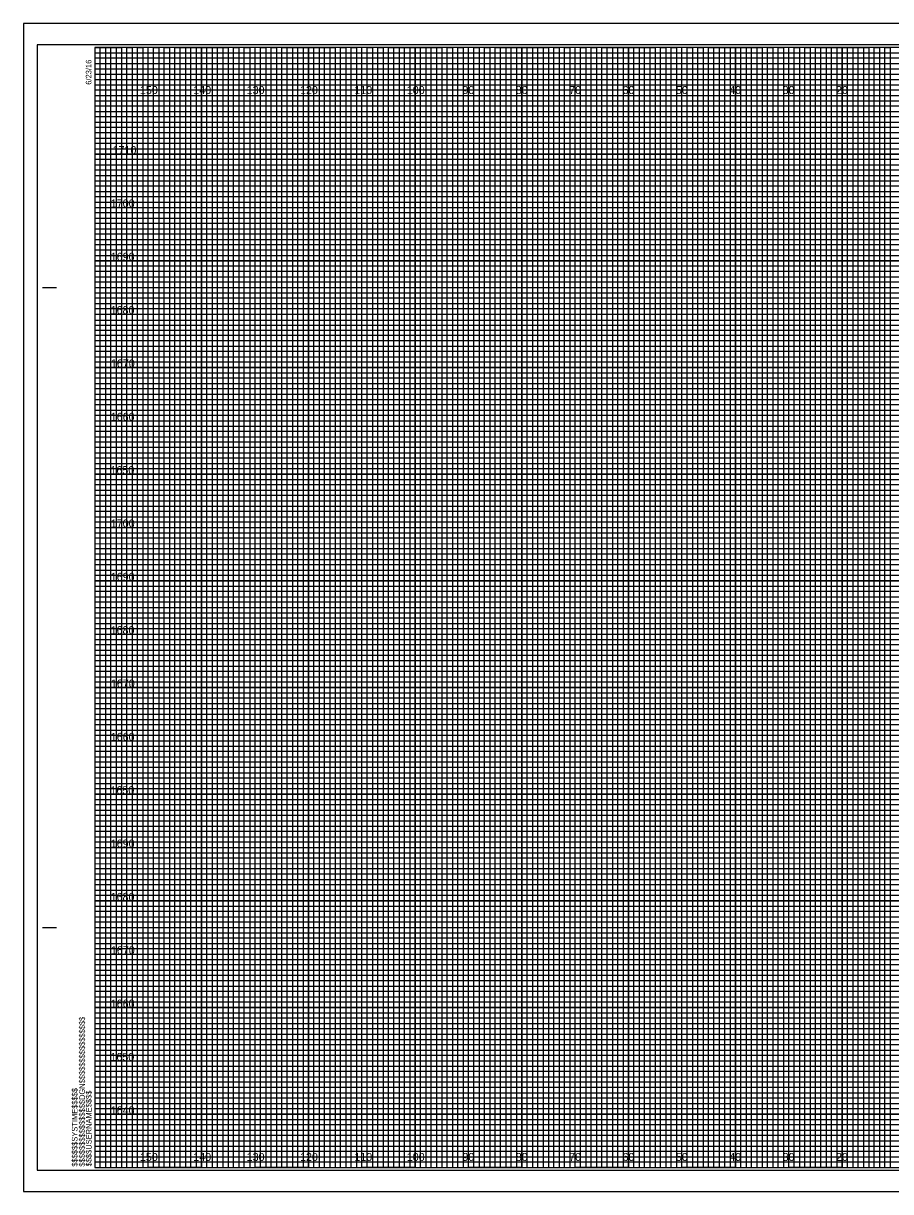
# Model space of a CAD drawing. Extents: x -13 to 323, y -5 to 2414.
# Drawn here: x -13.4 to 149.1, y 1535.5 to 1754.5 of the extents above; entities that cross this region are included whole.
import ezdxf

# ---------------------------------------------------------------- set-up
doc = ezdxf.new("R2010")
doc.units = 0
for name, color, linetype in [('Prop XS Elevation Labels', 7, 'Continuous'), ('Prop XS Offset Labels', 7, 'Continuous'), ('Sheet Cross Section CELL', 7, 'Continuous'), ('Sheet Cross Section Grid Major CELL', 7, 'Continuous'), ('Sheet Cross Section Grid Middle CELL', 7, 'Continuous'), ('Sheet Cross Section Grid Minor 1 CELL', 7, 'Continuous'), ('Sheet Cross Section Grid Minor 2 CELL', 7, 'Continuous'), ('Sheet Cutting Line CELL', 7, 'Continuous'), ('Sheet DOT Grid CELL', 7, 'Continuous'), ('Sheet Plot Border Inside CELL', 7, 'Continuous'), ('Sheet Plot Border Outside CELL', 7, 'Continuous')]:
    doc.layers.add(name, color=color, linetype=linetype)

msp = doc.modelspace()

# ---------------------------------------------------------------- linework, layer by layer
at = {"layer": 'Sheet Cross Section CELL'}
for p, q in [((-9.8, 1705), (-7.3, 1705)), ((-9.7, 1705), (-7.2, 1705)), ((-9.8, 1585), (-7.3, 1585)), ((-9.7, 1585), (-7.2, 1585)), ((0, 1540), (0, 1540)), ((0, 1540), (0, 1540)), ((0, 1540), (0, 1540)), ((0, 1540), (0, 1540)), ((0, 1540), (0, 1540)), ((0, 1540), (0, 1540)), ((0, 1540), (0, 1540))]:
    msp.add_line(p, q, dxfattribs=at)
msp.add_lwpolyline([(320, 1750), (0, 1750), (0, 1540), (320, 1540)], close=True, dxfattribs=at)
at = {"layer": 'Sheet Cross Section Grid Major CELL'}
for p, q in [((10, 1750), (0, 1750)), ((10, 1540), (10, 1750)), ((30, 1750), (20, 1750)), ((20, 1750), (20, 1540)), ((30, 1540), (30, 1750)), ((50, 1750), (40, 1750)), ((40, 1750), (40, 1540)), ((50, 1540), (50, 1750)), ((70, 1750), (60, 1750)), ((60, 1750), (60, 1540)), ((70, 1540), (70, 1750)), ((90, 1750), (80, 1750)), ((80, 1750), (80, 1540)), ((90, 1540), (90, 1750)), ((110, 1750), (100, 1750)), ((100, 1750), (100, 1540)), ((110, 1540), (110, 1750)), ((130, 1750), (120, 1750)), ((120, 1750), (120, 1540)), ((130, 1540), (130, 1750)), ((150, 1750), (140, 1750)), ((140, 1750), (140, 1540)), ((20, 1540), (10, 1540)), ((40, 1540), (30, 1540)), ((60, 1540), (50, 1540)), ((80, 1540), (70, 1540)), ((100, 1540), (90, 1540)), ((120, 1540), (110, 1540)), ((140, 1540), (130, 1540))]:
    msp.add_line(p, q, dxfattribs=at)
for points in [[(0, 1740), (320, 1740), (320, 1730), (0, 1730)], [(0, 1720), (320, 1720), (320, 1710), (0, 1710)], [(0, 1700), (320, 1700), (320, 1690), (0, 1690)], [(0, 1680), (320, 1680), (320, 1670), (0, 1670)], [(0, 1660), (320, 1660), (320, 1650), (0, 1650)], [(0, 1640), (320, 1640), (320, 1630), (0, 1630)], [(0, 1620), (320, 1620), (320, 1610), (0, 1610)], [(0, 1600), (320, 1600), (320, 1590), (0, 1590)], [(0, 1580), (320, 1580), (320, 1570), (0, 1570)], [(0, 1560), (320, 1560), (320, 1550), (0, 1550)]]:
    msp.add_lwpolyline(points, dxfattribs=at)
at = {"layer": 'Sheet Cross Section Grid Middle CELL'}
for points in [[(0, 1750), (5, 1750), (5, 1540), (15, 1540), (15, 1750), (25, 1750), (25, 1540), (35, 1540), (35, 1750), (45, 1750), (45, 1540), (55, 1540), (55, 1750), (65, 1750), (65, 1540), (75, 1540), (75, 1750), (85, 1750), (85, 1540), (95, 1540), (95, 1750), (105, 1750), (105, 1540), (115, 1540), (115, 1750), (125, 1750), (125, 1540), (135, 1540), (135, 1750), (145, 1750), (145, 1540), (155, 1540)], [(0, 1745), (275, 1745)], [(0, 1725), (320, 1725), (320, 1735), (0, 1735)], [(0, 1705), (320, 1705), (320, 1715), (0, 1715)], [(0, 1685), (320, 1685), (320, 1695), (0, 1695)], [(0, 1665), (320, 1665), (320, 1675), (0, 1675)], [(0, 1645), (320, 1645), (320, 1655), (0, 1655)], [(0, 1625), (320, 1625), (320, 1635), (0, 1635)], [(0, 1605), (320, 1605), (320, 1615), (0, 1615)], [(0, 1585), (320, 1585), (320, 1595), (0, 1595)], [(0, 1565), (320, 1565), (320, 1575), (0, 1575)], [(0, 1545), (320, 1545), (320, 1555), (0, 1555)]]:
    msp.add_lwpolyline(points, dxfattribs=at)
at = {"layer": 'Sheet Cross Section Grid Minor 1 CELL'}
for p, q in [((0, 1749), (260, 1749)), ((260, 1747.98), (0, 1747.98)), ((0, 1747.98), (0, 1747)), ((0, 1747), (260, 1747)), ((260, 1745.89), (0, 1745.89)), ((0, 1745.89), (0, 1744)), ((0, 1744), (320, 1744))]:
    msp.add_line(p, q, dxfattribs=at)
for points in [[(0, 1743), (270, 1743), (320, 1743), (320, 1742), (0, 1742)], [(0, 1741), (320, 1741), (320, 1739), (0, 1739)], [(0, 1738), (320, 1738), (320, 1737), (0, 1736.98)], [(0, 1736), (320, 1736), (320, 1734), (0, 1734)], [(0, 1733), (320, 1733), (320, 1732), (0, 1732)], [(0, 1731), (320, 1731), (320, 1729), (0, 1729)], [(0, 1728), (320, 1728), (320, 1727), (0, 1727)], [(0, 1726), (320, 1726), (320, 1724), (0, 1724)], [(0, 1723), (320, 1723), (320, 1722), (0, 1722)], [(0, 1721), (320, 1721), (320, 1719), (0, 1719)], [(0, 1718), (320, 1718), (320, 1717), (0, 1717)], [(0, 1716), (320, 1716), (320, 1713.95), (320, 1713), (320, 1712), (0, 1712)], [(0, 1714), (320, 1714), (320, 1713), (0, 1713)], [(0, 1711), (320, 1711), (320, 1709), (0, 1709.03)], [(0, 1709.03), (320, 1709), (320, 1708), (0, 1708)], [(0, 1707), (320, 1707), (320, 1706), (0, 1706)], [(0, 1704), (320, 1704), (320, 1703), (0, 1703)], [(0, 1702), (320, 1702), (320, 1701), (0, 1701)], [(-0.07, 1698.89), (320, 1698.89), (320, 1697.88), (-0.07, 1697.88)], [(0, 1697), (320, 1697), (320, 1696), (0, 1696)], [(0, 1694), (320, 1694), (320, 1693), (0, 1693)], [(0, 1692), (320, 1692), (320, 1691), (0, 1691)], [(0, 1689), (320, 1689), (320, 1688), (0, 1688)], [(0, 1687), (320, 1687), (320, 1686), (0, 1686)], [(0, 1684), (320, 1684), (320, 1683), (0, 1683)], [(0, 1682), (320, 1682), (320, 1681), (0, 1681)], [(0, 1679), (320, 1679), (319.99, 1677.98), (0, 1678)], [(0, 1677), (320, 1677), (320, 1676), (0, 1676)], [(0, 1674), (320, 1674), (320, 1673), (0, 1673)], [(0, 1672), (320, 1672), (320, 1671), (0, 1671)], [(0, 1669), (320, 1669), (320, 1668), (0, 1668)], [(0, 1667), (320, 1667), (320, 1666), (0, 1666)], [(0, 1664), (320, 1664), (320, 1663), (0, 1663)], [(0, 1662), (320, 1662), (320, 1661), (0, 1661)], [(0, 1659), (320, 1659), (320, 1658), (0, 1658)], [(0, 1656.99), (320.07, 1656.91), (320, 1656), (0, 1656)], [(0, 1654), (320, 1654), (320, 1653), (0, 1653)], [(0, 1652), (320, 1652), (320, 1651), (0, 1651)], [(0, 1649), (320, 1649), (320, 1648), (0, 1648)], [(0, 1647), (320, 1647), (320, 1646), (0, 1646)], [(0, 1644), (320, 1644), (320, 1643), (0, 1643)], [(0, 1642), (320, 1642), (320, 1641), (0, 1641)], [(0, 1639), (320, 1639), (320, 1638), (0, 1638)], [(0, 1637), (320, 1637), (320, 1636), (0, 1636)], [(0, 1634), (320, 1634), (320, 1633), (0, 1633)], [(0, 1632), (320, 1632), (320, 1631), (0, 1631)], [(0, 1629), (320, 1629), (320, 1628), (0, 1628)], [(0, 1627), (320, 1627), (320, 1626), (0, 1626)], [(0, 1624), (320, 1624), (320, 1623), (0, 1623)], [(0, 1622), (320, 1622), (320, 1621), (0, 1621)], [(0, 1619), (320, 1619), (319.99, 1617.98), (0, 1618)], [(0, 1617), (320, 1617), (320, 1616), (0, 1616)], [(0, 1614), (320, 1614), (320, 1613), (0, 1613)], [(0, 1612), (320, 1612), (320, 1611), (0, 1611)], [(0, 1609), (320, 1609), (320, 1608), (0, 1608)], [(0, 1607), (320, 1607), (320, 1606), (0, 1606)], [(0, 1604), (320, 1604), (320, 1603), (0, 1603)], [(0, 1602), (320, 1602), (320, 1601), (0, 1601)], [(0, 1599), (320, 1599), (320, 1598), (0, 1598)], [(0, 1596.99), (320.07, 1596.91), (320, 1596), (0, 1596)], [(0, 1594), (320, 1594), (320, 1593), (0, 1593)], [(0, 1592), (320, 1592), (320, 1591), (0, 1591)], [(0, 1589), (320, 1589), (320, 1588), (0, 1588)], [(0, 1587), (320, 1587), (320, 1586), (0, 1586)], [(0, 1584), (320, 1584), (320, 1583), (0, 1583)], [(0, 1582), (320, 1582), (320, 1581), (0, 1581)], [(0, 1579), (320, 1579), (320, 1578), (0, 1578)], [(0, 1577), (320, 1577), (320, 1576), (0, 1576)], [(0, 1574), (320, 1574), (320, 1573), (0, 1573)], [(0, 1572), (320, 1572), (320, 1571), (0, 1571)], [(0, 1569), (320, 1569), (320, 1568), (0, 1568)], [(0, 1567), (320, 1567), (320, 1566), (0, 1566)], [(0, 1564), (320, 1564), (320, 1563), (0, 1563)], [(0, 1562), (320, 1562), (320, 1561), (0, 1561)], [(0, 1559), (320, 1559), (320, 1558), (0, 1558)], [(0, 1557), (320, 1557), (320, 1556), (0, 1556)], [(0, 1554), (320, 1554), (320, 1553), (0, 1553)], [(0, 1552), (320, 1552), (320, 1551), (0, 1551)], [(0, 1549), (320, 1549), (320, 1548), (0, 1548)], [(0, 1547), (320, 1547), (320, 1546), (0, 1546)], [(0, 1544), (320, 1544), (320, 1543), (0, 1543)], [(0, 1542), (320, 1542), (320, 1541), (0, 1541)]]:
    msp.add_lwpolyline(points, dxfattribs=at)
at = {"layer": 'Sheet Cross Section Grid Minor 2 CELL'}
for points in [[(0, 1540), (1, 1540), (1, 1750), (2, 1750), (2, 1540)], [(2, 1540), (3, 1540), (3, 1750), (4, 1750), (4, 1540)], [(5, 1540), (6, 1540), (6, 1750), (7, 1750), (7, 1540)], [(7, 1540), (8, 1540), (8, 1750), (9, 1750), (9, 1540)], [(10, 1540), (11, 1540), (11, 1750), (12, 1750), (12, 1540)], [(12, 1540), (13, 1540), (13, 1750), (14, 1750), (14, 1540)], [(15, 1540), (16, 1540), (16, 1750), (17, 1750), (17, 1540)], [(17, 1540), (18, 1540), (18, 1750), (19, 1750), (19, 1540)], [(20, 1540), (21, 1540), (21, 1750), (22, 1750), (22, 1540)], [(22, 1540), (23, 1540), (23, 1750), (24, 1750), (24, 1540)], [(25, 1540), (26, 1540), (26, 1750), (27, 1750), (27, 1540)], [(27, 1540), (28, 1540), (28, 1750), (29, 1750), (29, 1540)], [(30, 1540), (31, 1540), (31, 1750), (32, 1750), (32, 1540)], [(32, 1540), (33, 1540), (33, 1750), (34, 1750), (34, 1540)], [(35, 1540), (36, 1540), (36, 1750), (37, 1750), (37, 1540)], [(37, 1540), (38, 1540), (38, 1750), (39, 1750), (39, 1540)], [(40, 1540), (41, 1540), (41, 1750), (42, 1750), (42, 1540)], [(42, 1540), (43, 1540), (43, 1750), (44, 1750), (44, 1540)], [(45, 1540), (46, 1540), (46, 1750), (47, 1750), (47, 1540)], [(47, 1540), (48, 1540), (48, 1750), (49, 1750), (49, 1540)], [(50, 1540), (51, 1540), (51, 1750), (52, 1750), (52, 1540)], [(52, 1540), (53, 1540), (53, 1750), (54, 1750), (54, 1540)], [(55, 1540), (56, 1540), (56, 1750), (57, 1750), (57, 1540)], [(57, 1540), (58, 1540), (58, 1750), (59, 1750), (59, 1540)], [(60, 1540), (61, 1540), (61, 1750), (62, 1750), (62, 1540)], [(62, 1540), (63, 1540), (63, 1750), (64, 1750), (64, 1540)], [(65, 1540), (66, 1540), (66, 1750), (67, 1750), (67, 1540)], [(67, 1540), (68, 1540), (68, 1750), (69, 1750), (69, 1540)], [(70, 1540), (71, 1540), (71, 1750), (72, 1750), (72, 1540)], [(72, 1540), (73, 1540), (73, 1750), (74, 1750), (74, 1540)], [(75, 1540), (76, 1540), (76, 1750), (77, 1750), (77, 1540)], [(77, 1540), (78, 1540), (78, 1750), (79, 1750), (79, 1540)], [(80, 1540), (81, 1540), (81, 1750), (82, 1750), (82, 1540)], [(82, 1540), (83, 1540), (83, 1750), (84, 1750), (84, 1540)], [(85, 1540), (86, 1540), (86, 1750), (87, 1750), (87, 1540)], [(87, 1540), (88, 1540), (88, 1750), (89, 1750), (89, 1540)], [(90, 1540), (91, 1540), (91, 1750), (92, 1750), (92, 1540)], [(92, 1540), (93, 1540), (93, 1750), (94, 1750), (94, 1540)], [(95, 1540), (96, 1540), (96, 1750), (97, 1750), (97, 1540)], [(97, 1540), (98, 1540), (98, 1750), (99, 1750), (99, 1540)], [(100, 1540), (101, 1540), (101, 1750), (102, 1750), (102, 1540)], [(102, 1540), (103, 1540), (103, 1750), (104, 1750), (104, 1540)], [(105, 1540), (106, 1540), (106, 1750), (107, 1750), (107, 1540)], [(107, 1540), (108, 1540), (108, 1750), (109, 1750), (109, 1540)], [(110, 1540), (111, 1540), (111, 1750), (112, 1750), (112, 1540)], [(112, 1540), (113, 1540), (113, 1750), (114, 1750), (114, 1540)], [(115, 1540), (116, 1540), (116, 1750), (117, 1750), (117, 1540)], [(117, 1540), (118, 1540), (118, 1750), (119, 1750), (119, 1540)], [(120, 1540), (121, 1540), (121, 1750), (122, 1750), (122, 1540)], [(122, 1540), (123, 1540), (123, 1750), (124, 1750), (124, 1540)], [(125, 1540), (126, 1540), (126, 1750), (127, 1750), (127, 1540)], [(127, 1540), (128, 1540), (128, 1750), (129, 1750), (129, 1540)], [(130, 1540), (131, 1540), (131, 1750), (132, 1750), (132, 1540)], [(132, 1540), (133, 1540), (133, 1750), (134, 1750), (134, 1540)], [(135, 1540), (136, 1540), (136, 1750), (137, 1750), (137, 1540)], [(137, 1540), (138, 1540), (138, 1750), (139, 1750), (139, 1540)], [(140, 1540), (141, 1540), (141, 1750), (142, 1750), (142, 1540)], [(142, 1540), (143, 1540), (143, 1750), (144, 1750), (144, 1540)], [(145, 1540), (146, 1540), (146, 1750), (147, 1750), (147, 1540)], [(147, 1540), (148, 1540), (148, 1750), (149, 1750), (149, 1540)]]:
    msp.add_lwpolyline(points, dxfattribs=at)
at = {"layer": 'Sheet Cutting Line CELL'}
for p, q in [((323.3, 1754.5), (-13.4, 1754.5)), ((-13.4, 1754.5), (-13.4, 1535.5)), ((-13.4, 1535.5), (323.3, 1535.5))]:
    msp.add_line(p, q, dxfattribs=at)
at = {"layer": 'Sheet DOT Grid CELL'}
for p, q in [((10, 1540), (10, 1750)), ((20, 1540), (20, 1750)), ((30, 1540), (30, 1750)), ((40, 1540), (40, 1750)), ((50, 1540), (50, 1750)), ((60, 1540), (60, 1750)), ((70, 1540), (70, 1750)), ((80, 1540), (80, 1750)), ((90, 1540), (90, 1750)), ((100, 1540), (100, 1750)), ((110, 1540), (110, 1750)), ((120, 1540), (120, 1750)), ((130, 1540), (130, 1750)), ((140, 1540), (140, 1750)), ((0, 1740), (320, 1740)), ((0, 1730), (320, 1730)), ((0, 1720), (320, 1720)), ((0, 1710), (320, 1710)), ((0, 1700), (320, 1700)), ((0, 1690), (320, 1690)), ((0, 1680), (320, 1680)), ((0, 1670), (320, 1670)), ((0, 1660), (320, 1660)), ((0, 1650), (320, 1650)), ((0, 1640), (320, 1640)), ((0, 1630), (320, 1630)), ((0, 1620), (320, 1620)), ((0, 1610), (320, 1610)), ((0, 1600), (320, 1600)), ((0, 1590), (320, 1590)), ((0, 1580), (320, 1580)), ((0, 1570), (320, 1570)), ((0, 1560), (320, 1560)), ((0, 1550), (320, 1550))]:
    msp.add_line(p, q, dxfattribs=at)
at = {"layer": 'Sheet Plot Border Inside CELL'}
msp.add_lwpolyline([(-10.8, 1539.5), (322.4, 1539.5), (322.4, 1750.5), (-10.8, 1750.5)], close=True, dxfattribs=at)
at = {"layer": 'Sheet Plot Border Outside CELL'}
msp.add_lwpolyline([(-13.4, 1535.5), (323.3, 1535.5), (323.3, 1754.5), (-13.4, 1754.5)], close=True, dxfattribs=at)

# ---------------------------------------------------------------- texts
at = {"layer": 'Prop XS Elevation Labels'}
for s, p in [('1710', (3.31, 1730)), ('1700', (2.98, 1720)), ('1690', (2.97, 1710)), ('1680', (2.95, 1700)), ('1670', (3, 1690)), ('1660', (2.97, 1680)), ('1650', (2.92, 1670)), ('1700', (2.98, 1660)), ('1690', (2.97, 1650)), ('1680', (2.95, 1640)), ('1670', (3, 1630)), ('1660', (2.97, 1620)), ('1650', (2.92, 1610)), ('1690', (2.97, 1600)), ('1680', (2.95, 1590)), ('1670', (3, 1580)), ('1660', (2.97, 1570)), ('1650', (2.92, 1560)), ('1640', (2.97, 1550))]:
    msp.add_text(s, height=1.5, dxfattribs=at).set_placement(p)
at = {"layer": 'Prop XS Offset Labels'}
for s, p in [('150', (8.44, 1741.25)), ('140', (18.44, 1741.25)), ('130', (28.44, 1741.25)), ('120', (38.44, 1741.25)), ('110', (48.62, 1741.25)), ('100', (58.44, 1741.25)), ('90', (68.86, 1741.25)), ('80', (78.86, 1741.25)), ('70', (88.86, 1741.25)), ('60', (98.86, 1741.25)), ('50', (108.86, 1741.25)), ('40', (118.86, 1741.25)), ('30', (128.86, 1741.25)), ('20', (138.86, 1741.25)), ('150', (8.44, 1541.25)), ('140', (18.44, 1541.25)), ('130', (28.44, 1541.25)), ('120', (38.44, 1541.25)), ('110', (48.62, 1541.25)), ('100', (58.44, 1541.25)), ('90', (68.86, 1541.25)), ('80', (78.86, 1541.25)), ('70', (88.86, 1541.25)), ('60', (98.86, 1541.25)), ('50', (108.86, 1541.25)), ('40', (118.86, 1541.25)), ('30', (128.86, 1541.25)), ('20', (138.86, 1541.25))]:
    msp.add_text(s, height=1.5, dxfattribs=at).set_placement(p)
at = {"layer": 'Sheet Cross Section CELL'}
for s, p in [('6/23/16', (-0.65, 1743)), ('$$$$$$$$$$$$$$$$DGN$$$$$$$$$$$$$$$$', (-1.88, 1540.18)), ('$$$$$$SYSTIME$$$$$', (-3.26, 1540.18)), ('$$$$USERNAME$$$$', (-0.62, 1540.23))]:
    msp.add_text(s, height=1.05, rotation=90, dxfattribs=at).set_placement(p)

doc.saveas('drawing.dxf')
